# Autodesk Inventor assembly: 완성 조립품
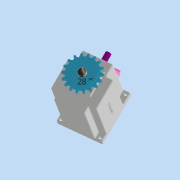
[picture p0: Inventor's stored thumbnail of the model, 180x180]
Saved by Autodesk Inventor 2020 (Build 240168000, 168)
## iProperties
Created: 2022-01
Part Number: 완성 조립품
Document SubType Name: Assembly
Designer: user
Author: user
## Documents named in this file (16)
- C:\Users\user\Desktop\720112V1006\완성 조립품.iam
- C:\Users\user\Desktop\720112V1006\멈춤나사 M3.ipt
- C:\Users\user\Desktop\720112V1006\메인 축.ipt
- C:\Users\user\Desktop\720112V1006\베어링 608.ipt
- C:\Users\user\Desktop\720112V1006\베어링 6003.ipt
- C:\Users\user\Desktop\720112V1006\본체.ipt
- C:\Users\user\Desktop\720112V1006\볼트 M4 x 10.ipt
- C:\Users\user\Desktop\720112V1006\부시.ipt
- C:\Users\user\Desktop\720112V1006\상부 캡.ipt
- C:\Users\user\Desktop\720112V1006\서브 축.ipt
- C:\Users\user\Desktop\720112V1006\스프로킷.ipt
- C:\Users\user\Desktop\720112V1006\슬라이더.ipt
- C:\Users\user\Desktop\720112V1006\오일 실 8 x 22 x 7.ipt
- C:\Users\user\Desktop\720112V1006\오일 실 17 x 32 x 8.ipt
- C:\Users\user\Desktop\720112V1006\커버.ipt
- C:\Users\user\Desktop\720112V1006\키 5 x 5.ipt
